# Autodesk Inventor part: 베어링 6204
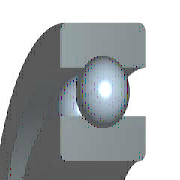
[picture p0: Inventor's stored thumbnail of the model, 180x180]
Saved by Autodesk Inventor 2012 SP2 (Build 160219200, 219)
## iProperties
IsCustomPart: 0
Manager: KYOUNG IL JANG
Company: 한국ATC센터
Created: 2009-02
Part Number: 베어링 6204
Material: Steel, Mild
Description: 깊은 그루브 볼 베어링
Document SubType Name: Modeling
Standard: KS B 2023
Standards Organization: KS
Language: ko-KR
Size Designation: 6204 - 20 x 47 x 14
Categories: <MemberInstance><Categories><Category DisplayName="샤프트 부품" InternalName="7f7aeb1f-a693-4053-b835-cee3144e0d98" Mnemonic="SHFT"><Category DisplayName="베어링" Inter
Density: 1 g/cm^3
Checked By: KYOUNG IL JANG
Vendor: CBT Solutions
Designer: KYOUNG IL JANG
Author: KYOUNG IL JANG
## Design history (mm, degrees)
revolve "본체" stored, may be unused: angle "d6" = 90 deg
revolve "볼" stored, may be unused: angle "d7" = 90 deg
pattern_circular "IDS_ARRAYBALL[SIMPL:T]" dims angle "d3" = 360 deg
body "Solid1"
sketch "스케치" dims "d0" = 7.02 (= -0.26 x WD + 0.26 x BD)
  geometry: L1 (3.49, 16.75)-(10.51, 16.75); L2 (7, 16.75)-(7, 13.24); L3 (7, 16.75)-(7, 20.26); L4 (4.392, 14.401)-(0, 14.401); L5 (0, 10)-(14, 10); L6 (4.392, 19.099)-(0, 19.099); L7 (0, 23.5)-(14, 23.5); L8 (14, 10)-(14, 14.401); L9 (9.608, 14.401)-(14, 14.401); L10 (9.608, 19.099)-(14, 19.099); L11 (14, 23.5)-(14, 19.099); L12 (-1.4, 0)-(8.4, 0) reference; L13 (0, -0.3)-(0, 5.3) reference
  constraints: 22 end point, 4 point on line, 2 collinear, 2 perpendicular, 2 symmetric about line, 1 midpoint, 1 parallel, 14 other
  dimensions: "d9" = 20 diameter of L5 L12 (= WD); "d11" = 47 diameter of L7 L12 (= BD); "d12" = 14 distance between parallel lines of L8 L13 (= KB); "d13" = 28.802 diameter of L9 L12 (= 0.326 x BD + 0.674 x WD)
fillet "모깎기1" dims "d1" = 1 (= KRS)
other parameters: "WD" = 20 [user parameter; used in 5 equation terms], "BD" = 47 [user parameter; used in 5 equation terms], "KB" = 14 [user parameter; used in 1 equation term], "KRS" = 1 [user parameter; used in 1 equation term], "d4" = 0, "d5" = 0, "d8" = 0, "d14" = 0, "d15" = 0, "BBA" = 0 [user parameter], "BC0" = 6550000 [user parameter], "BC" = 1.27e+07 [user parameter], "BR" = 23.5 (= 0.5 x BD) [user parameter]
